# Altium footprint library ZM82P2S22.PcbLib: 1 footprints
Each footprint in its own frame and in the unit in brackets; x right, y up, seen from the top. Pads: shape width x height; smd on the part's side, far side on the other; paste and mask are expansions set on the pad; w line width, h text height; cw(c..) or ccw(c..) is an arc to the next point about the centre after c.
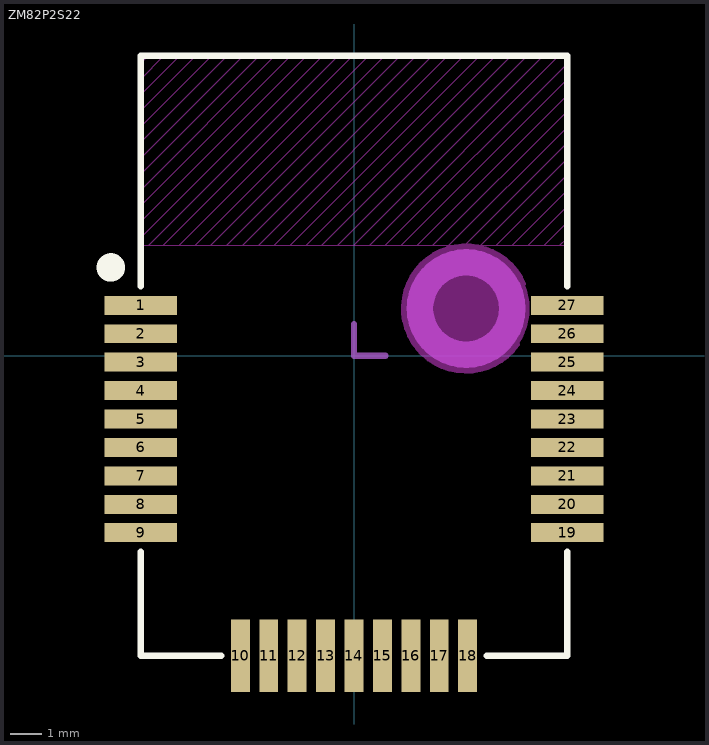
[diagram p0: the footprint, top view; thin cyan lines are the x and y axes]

## ZM82P2S22 [mm] "ZM82P2S22 Rev.A"
height 2.3
pads (28):
  rect 2.3x0.6 smd: 1(-6.75,1.6) 2(-6.75,0.7) 3(-6.75,-0.2) 4(-6.75,-1.1) 5(-6.75,-2) 6(-6.75,-2.9) 7(-6.75,-3.8) 8(-6.75,-4.7) 9(-6.75,-5.6) 19(6.75,-5.6) 20(6.75,-4.7) 21(6.75,-3.8) 22(6.75,-2.9) 23(6.75,-2) 24(6.75,-1.1) 25(6.75,-0.2) 26(6.75,0.7) 27(6.75,1.6)
  rect 0.6x2.3 smd: 10(-3.6,-9.5) 11(-2.7,-9.5) 12(-1.8,-9.5) 13(-0.9,-9.5) 14(0,-9.5) 15(0.9,-9.5) 16(1.8,-9.5) 17(2.7,-9.5) 18(3.6,-9.5)
  round 1.016 on Mech15 paste-0.508 mask+0.381: ""(3.55,1.5)
Top Layer keep-out:
  lines w0.025: 1.56,1.556 3.507,3.504 ; 1.596,1.09 4.008,3.502 ; 1.634,2.132 2.886,3.384 ; 1.723,0.715 4.342,3.334 ; 1.91,0.4 4.659,3.149 ; 2.089,0.077 4.96,2.948 ; 2.391,-0.123 5.164,2.649 ; 2.733,-0.284 5.364,2.347 ; 3.074,-0.445 5.33,1.811 ; 3.524,-0.497 5.32,1.299 ; 4.102,-0.421 5.247,0.724
  lines w0.127: 5.188,0.353 cw(c3.55,1.5) 5.391,2.281
Top Overlay:
  circle w0.5: c-7.7,2.8 r0.2
  lines w0.2: -6.75,-6.2 -6.75,-9.5 -4.2,-9.5 ; -6.75,2.2 -6.75,9.5 6.75,9.5 6.75,2.2 ; 4.2,-9.5 6.75,-9.5 6.75,-6.2
Keep-Out Layer:
  board cut-out: 1.55,1.5 1.55,1.303 1.627,0.917 1.778,0.553 1.996,0.225 2.275,-0.054 2.603,-0.272 2.967,-0.423 3.353,-0.5 3.55,-0.5 3.747,-0.5 4.133,-0.423 4.497,-0.272 4.825,-0.054 5.104,0.225 5.322,0.553 5.473,0.917 5.55,1.303 5.55,1.5 5.55,1.697 5.473,2.083 5.322,2.447 5.104,2.775 4.825,3.054 4.497,3.272 4.133,3.423 3.747,3.5 3.55,3.5 3.353,3.5 2.967,3.423 2.603,3.272 2.275,3.054 1.996,2.775 1.778,2.447 1.627,2.083 1.55,1.697
Keep-Out Layer:
  lines w0.025: -0.037,9.5 -6.037,3.5 ; 0.465,9.5 -5.534,3.5 ; 0.968,9.5 -5.032,3.5 ; 1.47,9.5 -4.53,3.5 ; 1.972,9.5 -4.028,3.5 ; 2.474,9.5 -3.526,3.5 ; 2.976,9.5 -3.024,3.5 ; 3.478,9.5 -2.522,3.5 ; 3.507,3.504 6.748,6.744 ; 3.98,9.5 -2.02,3.5 ; 4.008,3.502 6.748,6.242 ; 4.483,9.5 -1.517,3.5 ; 4.51,3.501 6.748,5.74 ; 4.985,9.5 -1.015,3.5 ; 5.012,3.502 6.748,5.238 ; 5.487,9.5 -0.513,3.5 ; 5.513,3.501 6.748,4.736 ; 5.991,9.502 5.989,9.5 ; 6.018,3.504 6.748,4.234 ; 6.491,9.499 0.491,3.5 ; 6.518,3.502 6.748,3.732 ; 6.748,7.246 3.002,3.5 ; 6.748,7.749 2.5,3.5 ; 6.748,8.251 1.998,3.5 ; 6.748,8.753 1.495,3.5 ; 6.749,9.256 0.993,3.5 ; -6.75,3.745 -0.995,9.5 ; -6.75,3.745 -6.75,3.5 -6.493,3.5 ; -6.75,3.745 -6.75,4.248 ; -6.75,4.248 -1.498,9.5 ; -6.75,4.248 -6.75,4.75 ; -6.75,4.75 -2,9.5 ; -6.75,4.75 -6.75,5.252 ; -6.75,5.252 -2.502,9.5 ; -6.75,5.252 -6.75,5.754 ; -6.75,5.754 -3.004,9.5 ; -6.75,5.754 -6.75,6.256 ; -6.75,6.256 -3.506,9.5 ; -6.75,6.256 -6.75,6.758 ; -6.75,6.758 -4.008,9.5 ; -6.75,6.758 -6.75,7.26 ; -6.75,7.26 -4.51,9.5 ; -6.75,7.26 -6.75,7.763 ; -6.75,7.763 -5.013,9.5 ; -6.75,7.763 -6.75,8.265 ; -6.75,8.265 -5.515,9.5 ; -6.75,8.265 -6.75,8.767 ; -6.75,8.767 -6.017,9.5 ; -6.75,8.767 -6.75,9.269 ; -6.75,9.269 -6.519,9.5 ; -6.75,9.269 -6.75,9.5 -6.519,9.5 ; -6.519,9.5 -6.017,9.5 ; -6.493,3.5 -0.493,9.5 ; -6.493,3.5 -6.037,3.5 ; -6.037,3.5 -5.534,3.5 ; -6.017,9.5 -5.515,9.5 ; -5.534,3.5 -5.032,3.5 ; -5.515,9.5 -5.013,9.5 ; -5.032,3.5 -4.53,3.5 ; -5.013,9.5 -4.51,9.5 ; -4.53,3.5 -4.028,3.5 ; -4.51,9.5 -4.008,9.5 ; -4.028,3.5 -3.526,3.5 ; -4.008,9.5 -3.506,9.5 ; -3.526,3.5 -3.024,3.5 ; -3.506,9.5 -3.004,9.5 ; -3.024,3.5 -2.522,3.5 ; -3.004,9.5 -2.502,9.5 ; -2.522,3.5 -2.02,3.5 ; -2.502,9.5 -2,9.5 ; -2.02,3.5 -1.517,3.5 ; -2,9.5 -1.498,9.5 ; -1.517,3.5 -1.015,3.5 ; -1.498,9.5 -0.995,9.5 ; -1.015,3.5 -0.513,3.5 ; -0.995,9.5 -0.493,9.5 ; -0.513,3.5 -0.011,3.5 ; -0.493,9.5 5.989,9.5 ; -0.011,3.5 5.989,9.5 ; -0.011,3.5 0.491,3.5 ; 0.491,3.5 0.993,3.5 ; 0.993,3.5 1.495,3.5 ; 1.495,3.5 1.998,3.5 ; 1.998,3.5 2.5,3.5 ; 2.5,3.5 3.002,3.5 ; 3.002,3.5 6.75,3.5 6.75,9.5 5.989,9.5
Mechanical 15:
  circle w0.838: c3.55,1.5 r1.46
  lines w0.2: 0,1 0,0 1,0
  text "各层禁止走线" at -2.632,4.339 h0.76
  text "天线区域" at -1.852,5.246 h0.76
Multi-Layer:
  pour cut-out: -6.75,3.5 6.75,3.5 6.75,9.5 -6.75,9.5
3D body: height 2.6, standoff 0, extent -6.75,-9.5 6.75,9.5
